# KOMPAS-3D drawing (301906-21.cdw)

Views: Вид 1, Вид 2, Вид 3, Вид 4
Referenced files: перегородка.cdw
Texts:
  Отражательная перегородка
  денис
  Текст на чертеже
  Размерные надписи
  Шероховатость
  Линия-выноска #1
  Линия-выноска #2
  Линия-выноска #3
  Отклонения формы и база
  Заголовок таблицы
  Ячейка таблицы
  Стрелка вида
  Обозначение изменения
  Фигурная скобка
  Номер узла
  Марка координационной оси
  VRCB
  Выносная надпись
  Обозначение узла
  Марка/позиционное обозначение с линией-выноской
  Марка/позиционное обозначение на линии
  Марка/позиционное обозначение без линии-выноски
  Баранов Д.А.
  СПбГТИ(ТУ)
  гр.364
  Сталь 12Х18Н10Т  Лист
Dimensions and other numbers on the sheet: 05.16.01.00.029; 7; 1310; 1850; 240; 5; 1:10; 1; 17.4; 05.16.01.01.000-; 0; 2; 3; 4; 6; 8; 9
